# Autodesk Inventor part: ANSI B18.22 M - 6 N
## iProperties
Comments: To add or edit properties for Autodesk Inventor files, use iProperties.
Created: 2004-08
Part Number: ANSI B18.22 M - 6 N
Vendor: Autodesk Inc.
Document SubType Name: Modeling
Designer: John Blackburn
Material: Default
Description: Plain Washer
Standard: ANSI B18.22 M
Alert: To add or edit properties for Autodesk Inventor files, use iProperties.
Control State: 0
Master: False
Checked Out: False
Shininess: 64.0
Length Units: 11269
Angle Units: 11279
Time Units: 11290
Mass Units: 11283
Length Display Precision: 3
Angle Display Precision: 2
Compacted: True
Classification: un/spsc 31161807
Density: 0.0
Volumn: 0.0
Area: 0.0
PropertySet Name: Model Information
Author: John Blackburn
Revision Number: 8
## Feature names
1. Body [Extrusion]
